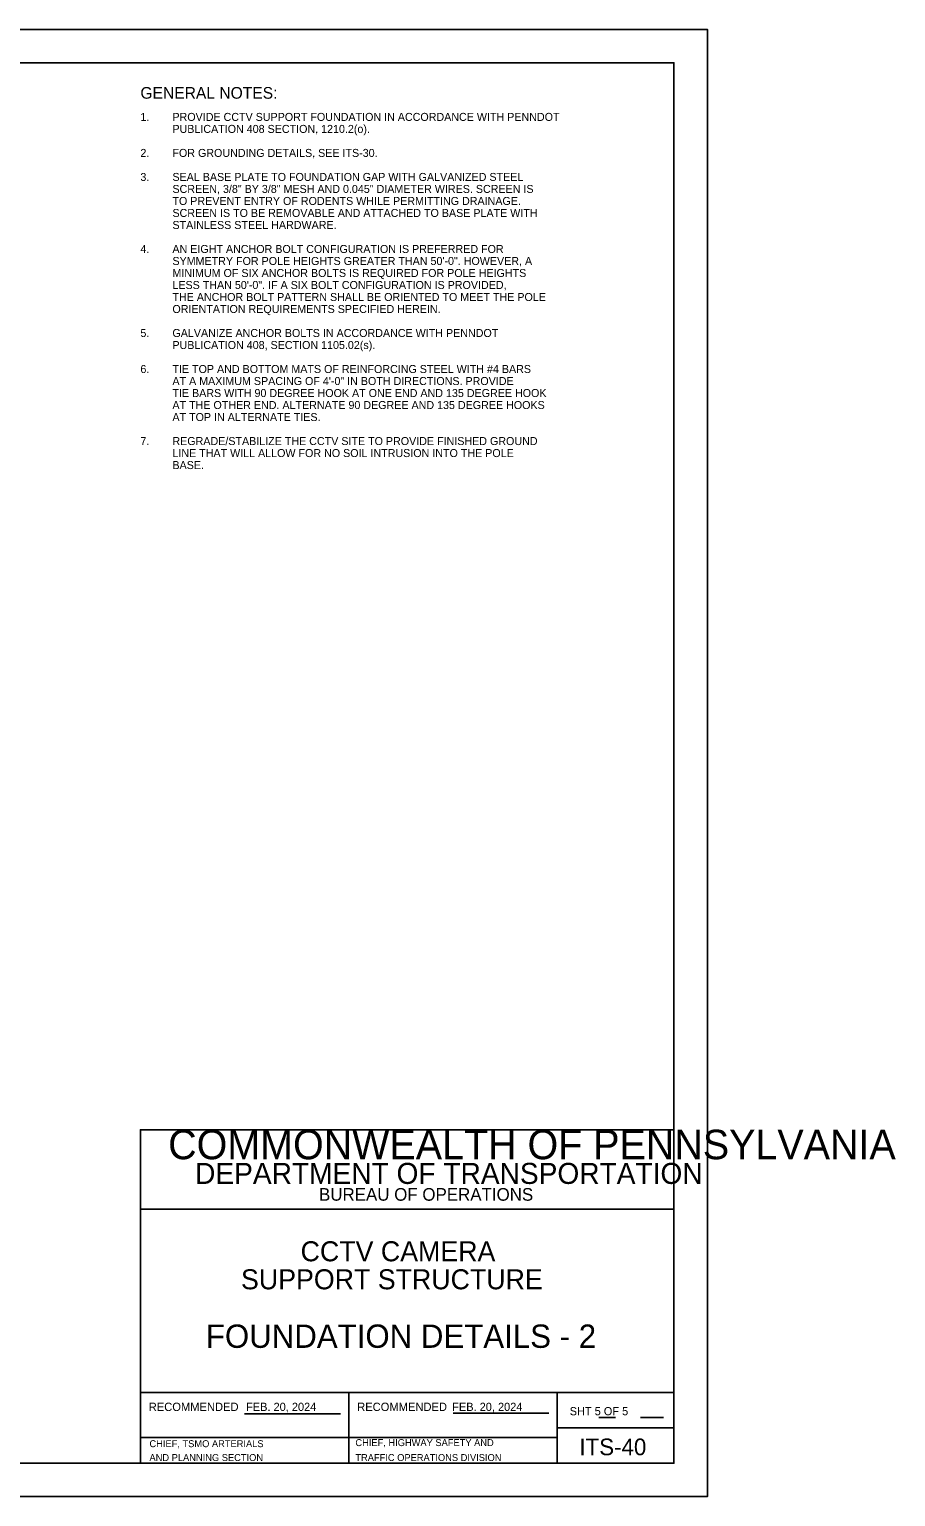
# Model space of a CAD drawing. Extents: x 1299104.6 to 1299141.4, y 239713.3 to 239735.3.
# Drawn here: x 1299128.46 to 1299141.45, y 239713.27 to 239735.27 of the extents above; entities that cross this region are included whole.
import ezdxf

# ---------------------------------------------------------------- set-up
doc = ezdxf.new("R2010")
doc.units = 0
for name, color, linetype in [('1', 7, 'Continuous'), ('2', 7, 'Continuous'), ('DIM TXT', 7, 'Continuous'), ('GS_plotshape_p', 7, 'Continuous'), ('Level 1', 7, 'Continuous'), ('PTEXT', 7, 'Continuous')]:
    doc.layers.add(name, color=color, linetype=linetype)

msp = doc.modelspace()

# ---------------------------------------------------------------- linework, layer by layer
at = {"layer": '1'}
for p, q in [((1299131.685, 239714.516), (1299133.122, 239714.516)), ((1299134.81, 239714.525), (1299136.247, 239714.525)), ((1299130.122, 239714.161), (1299133.247, 239714.161))]:
    msp.add_line(p, q, dxfattribs=at)
at = {"layer": 'GS_plotshape_p'}
msp.add_lwpolyline([(1299104.622, 239735.273), (1299138.622, 239735.273), (1299138.622, 239713.273), (1299104.622, 239713.273)], close=True, dxfattribs=at)
at = {"layer": 'Level 1'}
for p, q in [((1299130.122, 239714.835), (1299138.122, 239714.835)), ((1299133.247, 239713.773), (1299133.247, 239714.835)), ((1299136.372, 239713.773), (1299136.372, 239714.835)), ((1299136.997, 239714.46), (1299137.247, 239714.46)), ((1299137.622, 239714.46), (1299137.966, 239714.46)), ((1299136.372, 239714.304), (1299138.122, 239714.304)), ((1299133.247, 239714.161), (1299136.372, 239714.161))]:
    msp.add_line(p, q, dxfattribs=at)
for points in [[(1299138.122, 239713.773), (1299106.122, 239713.773), (1299106.122, 239734.773), (1299138.122, 239734.773)], [(1299130.122, 239713.773), (1299138.122, 239713.773), (1299138.122, 239718.773), (1299130.122, 239718.773)], [(1299130.122, 239718.773), (1299138.122, 239718.773), (1299138.122, 239717.585), (1299130.122, 239717.585)]]:
    msp.add_lwpolyline(points, close=True, dxfattribs=at)

# ---------------------------------------------------------------- texts
at = {"layer": '1'}
for s, height, p in [('COMMONWEALTH OF PENNSYLVANIA', 0.44223, (1299130.538, 239718.332)), ('DEPARTMENT OF TRANSPORTATION', 0.31514, (1299130.942, 239717.962)), ('BUREAU OF OPERATIONS', 0.18955, (1299132.8, 239717.71)), ('RECOMMENDED', 0.125, (1299130.247, 239714.557)), ('FEB. 20, 2024', 0.12303, (1299131.707, 239714.558)), ('RECOMMENDED', 0.125, (1299133.372, 239714.557)), ('FEB. 20, 2024', 0.12303, (1299134.797, 239714.558)), ('CHIEF, TSMO ARTERIALS ', 0.10417, (1299130.258, 239714.015)), ('CHIEF, HIGHWAY SAFETY AND ', 0.10417, (1299133.345, 239714.031)), ('AND PLANNING SECTION', 0.10417, (1299130.258, 239713.807)), ('TRAFFIC OPERATIONS DIVISION', 0.10417, (1299133.345, 239713.807))]:
    msp.add_text(s, height=height, dxfattribs=at).set_placement(p)
at = {"layer": '2'}
msp.add_text('SHT 5 OF 5', height=0.123, dxfattribs=at).set_placement((1299136.558, 239714.493))
at = {"layer": 'DIM TXT'}
for s, height, p in [('GENERAL NOTES:', 0.175, (1299130.122, 239734.233)), ('1.', 0.12, (1299130.122, 239733.9)), ('PROVIDE CCTV SUPPORT FOUNDATION IN ACCORDANCE WITH PENNDOT ', 0.12, (1299130.602, 239733.9)), ('PUBLICATION 408 SECTION, 1210.2(o).', 0.12, (1299130.602, 239733.72)), ('2.', 0.12, (1299130.122, 239733.36)), ('FOR GROUNDING DETAILS, SEE ITS-30.', 0.12, (1299130.602, 239733.36)), ('3.', 0.12, (1299130.122, 239733)), ('SEAL BASE PLATE TO FOUNDATION GAP WITH GALVANIZED STEEL ', 0.12, (1299130.602, 239733)), ('SCREEN, 3/8" BY 3/8" MESH AND 0.045" DIAMETER WIRES. SCREEN IS ', 0.12, (1299130.602, 239732.82)), ('TO PREVENT ENTRY OF RODENTS WHILE PERMITTING DRAINAGE. ', 0.12, (1299130.602, 239732.64)), ('SCREEN IS TO BE REMOVABLE AND ATTACHED TO BASE PLATE WITH ', 0.12, (1299130.602, 239732.46)), ('STAINLESS STEEL HARDWARE.', 0.12, (1299130.602, 239732.28)), ('4.', 0.12, (1299130.122, 239731.92)), ('AN EIGHT ANCHOR BOLT CONFIGURATION IS PREFERRED FOR ', 0.12, (1299130.602, 239731.92)), ('SYMMETRY FOR POLE HEIGHTS GREATER THAN 50\'-0". HOWEVER, A ', 0.12, (1299130.602, 239731.74)), ('MINIMUM OF SIX ANCHOR BOLTS IS REQUIRED FOR POLE HEIGHTS ', 0.12, (1299130.602, 239731.56)), ('LESS THAN 50\'-0". IF A SIX BOLT CONFIGURATION IS PROVIDED, ', 0.12, (1299130.602, 239731.38)), ('THE ANCHOR BOLT PATTERN SHALL BE ORIENTED TO MEET THE POLE ', 0.12, (1299130.602, 239731.2)), ('ORIENTATION REQUIREMENTS SPECIFIED HEREIN.', 0.12, (1299130.602, 239731.02)), ('5.', 0.12, (1299130.122, 239730.66)), ('GALVANIZE ANCHOR BOLTS IN ACCORDANCE WITH PENNDOT ', 0.12, (1299130.602, 239730.66)), ('PUBLICATION 408, SECTION 1105.02(s).', 0.12, (1299130.602, 239730.48)), ('6.', 0.12, (1299130.122, 239730.12)), ('AT A MAXIMUM SPACING OF 4\'-0" IN BOTH DIRECTIONS. PROVIDE ', 0.12, (1299130.602, 239729.94)), ('TIE TOP AND BOTTOM MATS OF REINFORCING STEEL WITH #4 BARS ', 0.12, (1299130.602, 239730.12)), ('TIE BARS WITH 90 DEGREE HOOK AT ONE END AND 135 DEGREE HOOK ', 0.12, (1299130.602, 239729.76)), ('AT THE OTHER END. ALTERNATE 90 DEGREE AND 135 DEGREE HOOKS ', 0.12, (1299130.602, 239729.58)), ('AT TOP IN ALTERNATE TIES.', 0.12, (1299130.602, 239729.4)), ('7.', 0.12, (1299130.122, 239729.04)), ('REGRADE/STABILIZE THE CCTV SITE TO PROVIDE FINISHED GROUND ', 0.12, (1299130.602, 239729.04)), ('LINE THAT WILL ALLOW FOR NO SOIL INTRUSION INTO THE POLE ', 0.12, (1299130.602, 239728.86)), ('BASE.', 0.12, (1299130.602, 239728.68))]:
    msp.add_text(s, height=height, dxfattribs=at).set_placement(p)
at = {"layer": 'PTEXT'}
for s, height, p in [('CCTV CAMERA', 0.3, (1299132.524, 239716.802)), ('SUPPORT STRUCTURE', 0.3, (1299131.63, 239716.382)), ('FOUNDATION DETAILS - 2', 0.35, (1299131.103, 239715.504)), ('ITS-40', 0.25, (1299136.704, 239713.894))]:
    msp.add_text(s, height=height, dxfattribs=at).set_placement(p)

doc.saveas('drawing.dxf')
